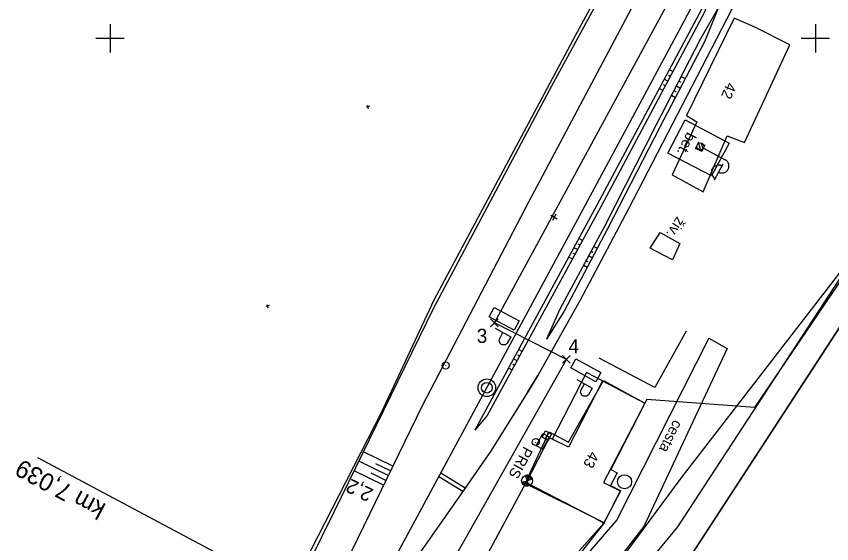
# Model space of a CAD drawing. Extents: x -795094 to -794639, y -1135368 to -1134681.
# Drawn here: x -794913.3 to -794797.7, y -1134971.7 to -1134896.9 of the extents above; entities that cross this region are included whole.
import ezdxf

# ---------------------------------------------------------------- set-up
doc = ezdxf.new("R2010")
doc.units = 0
for name, color, linetype in [('0381KM005-009P - Vrstva 1', 7, 'Continuous'), ('0381KM005-009P - Vrstva 16', 7, 'Continuous'), ('0381KM005-009P - Vrstva 17', 7, 'Continuous'), ('0381KM005-009P - Vrstva 23', 7, 'Continuous'), ('0381KM005-009P - Vrstva 25', 7, 'Continuous'), ('0381KM005-009P - Vrstva 28', 7, 'Continuous'), ('0381KM005-009P - Vrstva 33', 7, 'Continuous'), ('0381KM005-009P - Vrstva 4', 7, 'Continuous'), ('0381KM005-009P - Vrstva 43', 7, 'Continuous'), ('0381KM005-009P - Vrstva 48', 7, 'Continuous'), ('0381KM005-009P - Vrstva 49', 7, 'Continuous'), ('0381KM005-009P - Vrstva 51', 7, 'Continuous'), ('0381KM005-009P - Vrstva 55', 7, 'Continuous'), ('0381KM005-009P - Vrstva 57', 7, 'Continuous'), ('0381KM005-009P - Vrstva 7', 7, 'Continuous'), ('0381KM005-009P - Vrstva 8', 7, 'Continuous'), ('Default', 7, 'Continuous'), ('hran DP - hran DP', 7, 'Continuous'), ('krizky_1000 - Vrstva 1', 7, 'Continuous'), ('PSR_C2_1_Lomove_body_Strunkovice - Vrstva 60', 7, 'Continuous'), ('PSR_C2_1_trasa_Strunkovice - Kabelová trasa', 7, 'Continuous'), ('vyt_sit - stávající', 7, 'Continuous')]:
    doc.layers.add(name, color=color, linetype=linetype)

msp = doc.modelspace()

# ---------------------------------------------------------------- linework, layer by layer
at = {"layer": '0381KM005-009P - Vrstva 1'}
for points in [[(-794788.58, -1134840.28), (-794803.19, -1134868.16), (-794810.38, -1134881.86), (-794818.66, -1134897.6), (-794826.62, -1134912.5), (-794834.33, -1134926.85), (-794861.92, -1134977.99)], [(-794786.96, -1134841.36), (-794793.84, -1134858.32), (-794800.91, -1134874.12), (-794807.73, -1134887.87), (-794826.52, -1134924.29), (-794833.34, -1134937.13), (-794839.37, -1134947.86), (-794840.75, -1134950.16), (-794846.08, -1134958.61), (-794850.88, -1134965.55), (-794860.1, -1134978.74)]]:
    msp.add_lwpolyline(points, dxfattribs=at)
at = {"layer": '0381KM005-009P - Vrstva 16'}
for points in [[(-794818.48, -1134911.58), (-794812.2, -1134914.87), (-794814.71, -1134919.51), (-794820.93, -1134916.29), (-794818.48, -1134911.58)], [(-794822, -1134927.54), (-794819.21, -1134929.13), (-794820.25, -1134931.43), (-794823.42, -1134929.75), (-794822, -1134927.54)]]:
    msp.add_lwpolyline(points, dxfattribs=at)
at = {"layer": '0381KM005-009P - Vrstva 17'}
for points in [[(-794815.66, -1134915.11), (-794816.11, -1134916.05), (-794816.99, -1134915.63), (-794816.5, -1134914.67)], [(-794818.32, -1134941.56), (-794822.76, -1134949.53), (-794830.66, -1134945.36)], [(-794829.98, -1134968.8), (-794847.03, -1134987.93), (-794852.58, -1134984.56), (-794841.01, -1134963.01)]]:
    msp.add_lwpolyline(points, dxfattribs=at)
at = {"layer": '0381KM005-009P - Vrstva 23'}
for p, q in [((-794832.46, -1134947.42), (-794837.31, -1134956.85)), ((-794830.18, -1134948.61), (-794832.46, -1134947.42)), ((-794830.18, -1134948.61), (-794824.17, -1134951.75)), ((-794837.72, -1134956.67), (-794841.01, -1134963.01)), ((-794837.31, -1134956.85), (-794837.72, -1134956.67)), ((-794828.11, -1134961.66), (-794829.04, -1134963.44)), ((-794841.01, -1134963.01), (-794831.42, -1134967.99)), ((-794829.04, -1134963.44), (-794827.57, -1134964.21)), ((-794829.98, -1134968.8), (-794827.57, -1134964.21)), ((-794831.42, -1134967.99), (-794829.98, -1134968.8))]:
    msp.add_line(p, q, dxfattribs=at)
for points in [[(-794830.18, -1134948.61), (-794835.02, -1134958.03), (-794837.31, -1134956.85)], [(-794824.17, -1134951.75), (-794829.02, -1134961.18), (-794828.11, -1134961.66)]]:
    msp.add_lwpolyline(points, dxfattribs=at)
at = {"layer": '0381KM005-009P - Vrstva 25'}
for p, q in [((-794816.57, -1134914.92), (-794816.3, -1134915.84)), ((-794816.21, -1134914.85), (-794815.95, -1134915.69)), ((-794815.86, -1134915.58), (-794812.78, -1134917.23)), ((-794813.11, -1134917.85), (-794814.34, -1134920.14))]:
    msp.add_line(p, q, dxfattribs=at)
msp.add_lwpolyline([(-794838.64, -1134956.06), (-794837.76, -1134956.53), (-794838.71, -1134958.29), (-794839.59, -1134957.82), (-794838.64, -1134956.06)], dxfattribs=at)
msp.add_circle((-794816.3, -1134915.34), 0.5, dxfattribs=at)
for centre, start, end in [((-794813.25, -1134918.11), 241.7362, 61.7362), ((-794813.74, -1134918.99), 61.0336, 242.4387)]:
    msp.add_arc(centre, 1, start, end, dxfattribs=at)
at = {"layer": '0381KM005-009P - Vrstva 28'}
msp.add_line((-794839.66, -1134957.33), (-794839.61, -1134957.24), dxfattribs=at)
msp.add_circle((-794839.64, -1134957.28), 0.5, dxfattribs=at)
at = {"layer": '0381KM005-009P - Vrstva 33'}
for points in [[(-794842, -1134940.1), (-794842.71, -1134941.41), (-794846.26, -1134939.5), (-794845.55, -1134938.19)], [(-794830.42, -1134947.43), (-794831.15, -1134948.73), (-794834.66, -1134946.76), (-794833.94, -1134945.46)]]:
    msp.add_lwpolyline(points, close=True, dxfattribs=at)
for points in [[(-794845.4, -1134941.14), (-794843.2, -1134942.34)], [(-794843.69, -1134943.25), (-794843.93, -1134943.48), (-794844.4, -1134943.48), (-794844.59, -1134943.38), (-794844.85, -1134942.99), (-794844.78, -1134942.67)], [(-794844.78, -1134942.67), (-794844.29, -1134941.75)], [(-794843.2, -1134942.34), (-794843.69, -1134943.25)], [(-794833.84, -1134948.42), (-794831.66, -1134949.65)], [(-794833.25, -1134949.95), (-794832.74, -1134949.04)], [(-794831.66, -1134949.65), (-794832.17, -1134950.56)], [(-794832.17, -1134950.56), (-794832.41, -1134950.78), (-794832.88, -1134950.77), (-794833.07, -1134950.66), (-794833.32, -1134950.27), (-794833.25, -1134949.95)]]:
    msp.add_lwpolyline(points, dxfattribs=at)
at = {"layer": '0381KM005-009P - Vrstva 4'}
msp.add_line((-794840.75, -1134950.16), (-794839.37, -1134947.86), dxfattribs=at)
at = {"layer": '0381KM005-009P - Vrstva 43'}
msp.add_lwpolyline([(-794837.83, -1134955.94), (-794837.39, -1134956.18), (-794837.87, -1134957.06), (-794838.75, -1134956.58), (-794838.27, -1134955.7), (-794837.83, -1134955.94), (-794838.31, -1134956.82)], dxfattribs=at)
msp.add_circle((-794827.05, -1134962.91), 1, dxfattribs=at)
at = {"layer": '0381KM005-009P - Vrstva 48'}
for p, q in [((-794820.21, -1134904.73), (-794820.73, -1134904.46)), ((-794820.92, -1134906.06), (-794821.43, -1134905.78)), ((-794820.57, -1134905.4), (-794820.82, -1134905.26)), ((-794819.03, -1134905.41), (-794818.44, -1134905.72)), ((-794821.27, -1134906.72), (-794821.53, -1134906.58)), ((-794819.71, -1134906.75), (-794819.13, -1134907.05)), ((-794819.37, -1134906.08), (-794819.08, -1134906.23)), ((-794821.63, -1134907.38), (-794822.14, -1134907.11)), ((-794820.4, -1134908.08), (-794819.83, -1134908.38)), ((-794820.06, -1134907.42), (-794819.77, -1134907.56)), ((-794833.03, -1134928.67), (-794833.54, -1134928.39)), ((-794833.74, -1134929.98), (-794834.26, -1134929.71)), ((-794833.39, -1134929.32), (-794833.64, -1134929.19)), ((-794831.42, -1134929.54), (-794830.95, -1134929.79)), ((-794834.46, -1134931.3), (-794834.97, -1134931.03)), ((-794834.1, -1134930.64), (-794834.36, -1134930.51)), ((-794832.13, -1134930.86), (-794831.64, -1134931.12)), ((-794831.78, -1134930.2), (-794831.54, -1134930.33)), ((-794832.84, -1134932.18), (-794832.34, -1134932.45)), ((-794832.49, -1134931.52), (-794832.24, -1134931.65)), ((-794841.95, -1134945.08), (-794842.19, -1134944.95)), ((-794841.59, -1134944.42), (-794842.07, -1134944.15)), ((-794842.66, -1134946.4), (-794842.9, -1134946.26)), ((-794842.3, -1134945.74), (-794842.79, -1134945.47)), ((-794843.02, -1134947.05), (-794843.5, -1134946.79)), ((-794859.9, -1134960.7), (-794864.09, -1134958.66)), ((-794860.56, -1134962.05), (-794864.75, -1134960.01)), ((-794860.23, -1134961.37), (-794862.32, -1134960.35)), ((-794861.21, -1134963.4), (-794865.41, -1134961.35)), ((-794860.88, -1134962.72), (-794862.98, -1134961.7))]:
    msp.add_line(p, q, dxfattribs=at)
at = {"layer": '0381KM005-009P - Vrstva 49'}
for p, q in [((-794799.26, -1134845.15), (-794840.65, -1134923.24)), ((-794824.73, -1134883.39), (-794837.68, -1134907.33)), ((-794837.68, -1134907.33), (-794854.18, -1134938.37)), ((-794863.23, -1134909.63), (-794863.7, -1134909.77)), ((-794863.54, -1134909.46), (-794863.39, -1134909.94)), ((-794840.65, -1134923.24), (-794855.69, -1134952.03)), ((-794792.99, -1134928.57), (-794819.56, -1134969.3)), ((-794792.99, -1134928.57), (-794819.08, -1134962.42)), ((-794790.5, -1134931.65), (-794824.29, -1134983.58)), ((-794877.46, -1134937.92), (-794877.93, -1134938.06)), ((-794877.77, -1134937.75), (-794877.62, -1134938.23)), ((-794854.18, -1134938.37), (-794868.24, -1134967.15)), ((-794855.69, -1134952.03), (-794867.89, -1134977.13)), ((-794819.08, -1134962.42), (-794848.1, -1135001.61)), ((-794868.24, -1134967.15), (-794883.51, -1134998.27)), ((-794819.56, -1134969.3), (-794845.52, -1135000.83))]:
    msp.add_line(p, q, dxfattribs=at)
for points in [[(-794815.37, -1134894.44), (-794815.67, -1134896.21), (-794830.44, -1134923.9), (-794846.52, -1134953.51), (-794848.28, -1134955.61)], [(-794815.37, -1134894.44), (-794830.99, -1134923.68), (-794848.28, -1134955.61)], [(-794813.73, -1134895.61), (-794815.7, -1134900.49), (-794822, -1134912.52), (-794829.49, -1134927.01), (-794835.62, -1134938.73), (-794838.1, -1134942.66)], [(-794813.73, -1134895.61), (-794816.27, -1134900.06), (-794822.55, -1134912.27), (-794829.83, -1134926.6), (-794836.24, -1134938.45), (-794838.1, -1134942.66)]]:
    msp.add_lwpolyline(points, dxfattribs=at)
at = {"layer": '0381KM005-009P - Vrstva 51'}
for p, q in [((-794815.11, -1134942.54), (-794828.15, -1134968.34)), ((-794815.11, -1134942.54), (-794812.52, -1134944)), ((-794812.52, -1134944), (-794824.3, -1134969.27)), ((-794824.3, -1134969.27), (-794848.05, -1134999.57)), ((-794828.15, -1134968.34), (-794846.07, -1134989.06))]:
    msp.add_line(p, q, dxfattribs=at)
msp.add_lwpolyline([(-794871.74, -1135021.34), (-794845.86, -1135006.13), (-794837.37, -1134998.39), (-794824.29, -1134983.58), (-794790.5, -1134931.65), (-794766.19, -1134894.56)], dxfattribs=at)
at = {"layer": '0381KM005-009P - Vrstva 55'}
for points in [[(-794815.9, -1134921.79), (-794812.5, -1134913.85), (-794810.05, -1134914.8), (-794803.6, -1134900.93), (-794808.67, -1134898.39), (-794811.52, -1134897.15), (-794818.27, -1134910.96), (-794816.8, -1134911.86), (-794820.3, -1134919.39), (-794815.9, -1134921.79)], [(-794829.96, -1134968.76), (-794841.15, -1134963.17), (-794837.72, -1134955.82), (-794835, -1134957.3), (-794830.05, -1134948.55), (-794824.17, -1134951.78), (-794830.03, -1134963.03), (-794827.67, -1134964.22), (-794829.96, -1134968.76)]]:
    msp.add_lwpolyline(points, dxfattribs=at)
at = {"layer": '0381KM005-009P - Vrstva 7'}
for p, q in [((-794836.61, -1134925.64), (-794837.49, -1134925.16)), ((-794836.81, -1134924.96), (-794837.29, -1134925.84)), ((-794852.4, -1134946.37), (-794852.45, -1134946.46)), ((-794853.39, -1134962.19), (-794849.99, -1134964.27)), ((-794853.11, -1134961.66), (-794849.65, -1134963.78))]:
    msp.add_line(p, q, dxfattribs=at)
for centre, radius in [((-794852.42, -1134946.42), 0.5), ((-794846.58, -1134949.57), 1.25), ((-794846.58, -1134949.57), 0.752)]:
    msp.add_circle(centre, radius, dxfattribs=at)
at = {"layer": '0381KM005-009P - Vrstva 8'}
msp.add_line((-794867.87, -1134982.1), (-794910.23, -1134959.53), dxfattribs=at)
at = {"layer": 'hran DP - hran DP'}
for p, q in [((-794834.03, -1134899.62), (-794808.02, -1134851.51)), ((-794771.93, -1134898.11), (-794808.62, -1134952.39)), ((-794854.06, -1134937.12), (-794834.03, -1134899.62)), ((-794861.46, -1134953), (-794854.06, -1134937.12)), ((-794824.17, -1134951.78), (-794830.03, -1134963.03)), ((-794823.88, -1134951.22), (-794824.17, -1134951.78)), ((-794808.62, -1134952.39), (-794823.88, -1134951.22)), ((-794880.53, -1134990.11), (-794861.46, -1134953)), ((-794830.03, -1134963.03), (-794827.67, -1134964.22)), ((-794827.67, -1134964.22), (-794829.96, -1134968.76)), ((-794829.96, -1134968.76), (-794838.74, -1134979.98))]:
    msp.add_line(p, q, dxfattribs=at)
at = {"layer": 'krizky_1000 - Vrstva 1'}
for points in [[(-794900, -1134898), (-794900, -1134902)], [(-794800, -1134898), (-794800, -1134902)], [(-794902, -1134900), (-794898, -1134900)], [(-794802, -1134900), (-794798, -1134900)]]:
    msp.add_lwpolyline(points, dxfattribs=at)
at = {"layer": 'PSR_C2_1_Lomove_body_Strunkovice - Vrstva 60'}
for p, q in [((-794846.06, -1134940.92), (-794844.96, -1134939.82)), ((-794844.96, -1134940.92), (-794846.06, -1134939.82)), ((-794835.85, -1134946.1), (-794834.75, -1134945)), ((-794834.75, -1134946.1), (-794835.85, -1134945))]:
    msp.add_line(p, q, dxfattribs=at)
at = {"layer": 'PSR_C2_1_trasa_Strunkovice - Kabelová trasa'}
msp.add_lwpolyline([(-794859.57, -1134988.66), (-794835.3, -1134945.55), (-794845.51, -1134940.37), (-794776.44, -1134813), (-794772.18, -1134815.08)], dxfattribs=at)
at = {"layer": 'vyt_sit - stávající'}
for p, q in [((-794840.88, -1134962.76), (-794841.1, -1134962.03)), ((-794840.9, -1134962), (-794840.69, -1134962.7)), ((-794840.57, -1134962.06), (-794840.4, -1134962.62)), ((-794841.61, -1134962.98), (-794840.88, -1134962.76)), ((-794841.36, -1134962.91), (-794841.2, -1134963.46)), ((-794841.08, -1134962.82), (-794840.87, -1134963.52)), ((-794840.15, -1134962.54), (-794840.88, -1134962.76)), ((-794840.88, -1134962.76), (-794840.66, -1134963.5))]:
    msp.add_line(p, q, dxfattribs=at)
msp.add_circle((-794840.88, -1134962.76), 0.764, dxfattribs=at)
for radius, start, end in [(0.764, 16.1849, 106.5029), (0.765, 196.8737, 286.7672)]:
    msp.add_arc((-794840.88, -1134962.76), radius, start, end, dxfattribs=at)

# ---------------------------------------------------------------- texts
at = {"layer": '0381KM005-009P - Vrstva 16'}
for s, rotation, p in [('bet.', 242.5643, (-794818.15, -1134913.2)), ('živ.', 237.1152, (-794819.6, -1134925.19))]:
    msp.add_text(s, height=1.5, rotation=rotation, dxfattribs=at).set_placement(p)
at = {"layer": '0381KM005-009P - Vrstva 23'}
msp.add_text('žst. Strunkovice nad Volyňkou', height=8, rotation=245.663, dxfattribs=at).set_placement((-794771.54, -1134921.22))
at = {"layer": '0381KM005-009P - Vrstva 25'}
msp.add_text('PRIS', height=1.5, rotation=241.6619, dxfattribs=at).set_placement((-794841.32, -1134957.8))
at = {"layer": '0381KM005-009P - Vrstva 48'}
msp.add_text('2,2', height=2, rotation=154.0658, dxfattribs=at).set_placement((-794862.54, -1134964.05))
at = {"layer": '0381KM005-009P - Vrstva 51'}
msp.add_text('cesta', height=1.5, rotation=243.1983, dxfattribs=at).set_placement((-794820.06, -1134954.02))
at = {"layer": '0381KM005-009P - Vrstva 57'}
for s, rotation, p in [('42', 246.6586, (-794812.52, -1134906.14)), ('43', 242.7802, (-794831.94, -1134958.49))]:
    msp.add_text(s, height=1.5, rotation=rotation, dxfattribs=at).set_placement(p)
at = {"layer": '0381KM005-009P - Vrstva 8'}
msp.add_text('km 7,039', height=2.5, rotation=151.6652, dxfattribs=at).set_placement((-794900.42, -1134966.16))
at = {"layer": 'Default'}
for s, p in [('3', (-794848.01, -1134943.21)), ('4', (-794835.01, -1134944.69))]:
    msp.add_text(s, height=2, dxfattribs=at).set_placement(p)

doc.saveas('drawing.dxf')
